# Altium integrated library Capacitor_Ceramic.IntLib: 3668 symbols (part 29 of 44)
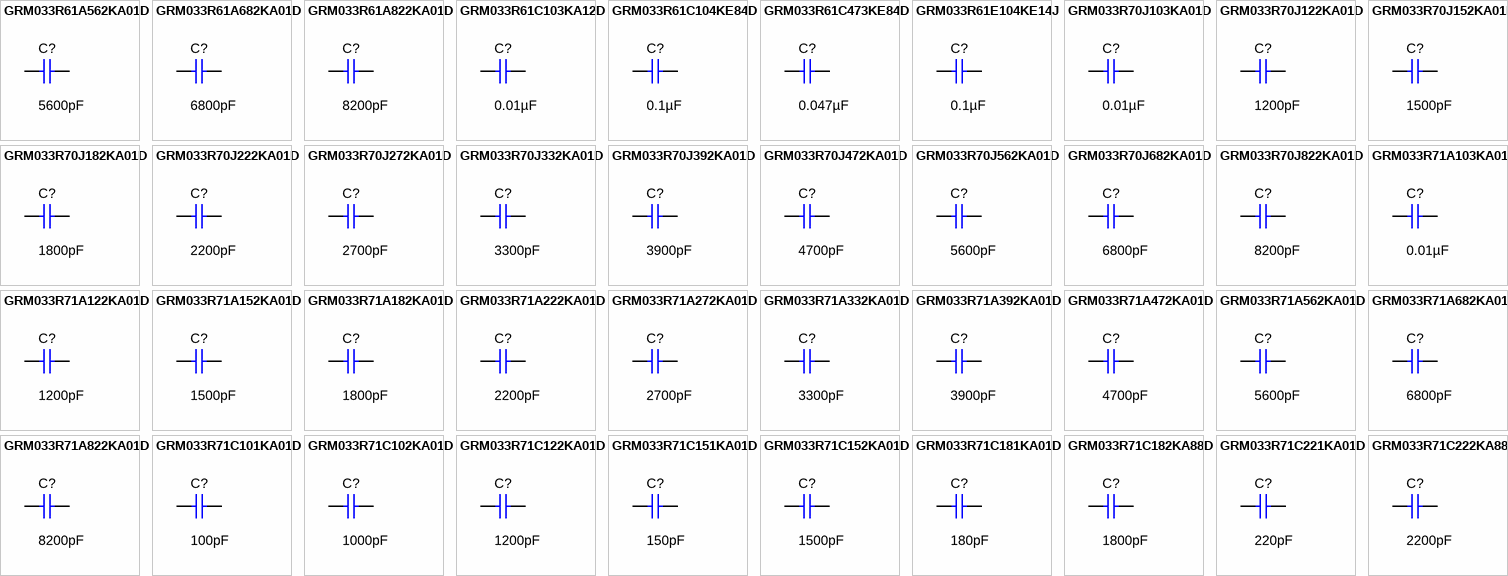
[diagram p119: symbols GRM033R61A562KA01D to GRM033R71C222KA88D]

## GRM033R70J182KA01D
designator C?  ValueDisplayed: 1800pF  (hidden comment: GRM033R70J182KA01D)
CAP, CERM, 1800 pF, 6.3 V,+/- 10%, X7R, 0201; Manufacturer: MuRata; Polarized: N; CompType: Capacitor; Value: 1800pF; U/M: EA; Cap_F: 0.0000000018; Tolerance_%: 10; VDC_V: 6.3; Value2: 6.3V; TaMin_C: -55; TaMax_C: 125; Cap_Case: 0201; SizeArea_mm2: 0.18; SizeAreaWB_mm2: 2.08; SizeX_mm: 0.6; SizeY_mm: 0.3; SizeZ_mm: 0.26; AEC Category: Q200
signal-integrity model Cap
simulation model Cap
footprint 0201
footprint 0201M
footprint 0201L
footprint 0201_Silk
pins: 1, 2

## GRM033R70J222KA01D
designator C?  ValueDisplayed: 2200pF  (hidden comment: GRM033R70J222KA01D)
CAP, CERM, 2200 pF, 6.3 V,+/- 10%, X7R, 0201; Manufacturer: MuRata; Polarized: N; CompType: Capacitor; Value: 2200pF; U/M: EA; Cap_F: 0.0000000022; Tolerance_%: 10; VDC_V: 6.3; Value2: 6.3V; TaMin_C: -55; TaMax_C: 125; Cap_Case: 0201; SizeArea_mm2: 0.18; SizeAreaWB_mm2: 2.08; SizeX_mm: 0.6; SizeY_mm: 0.3; SizeZ_mm: 0.26; AEC Category: Q200
signal-integrity model Cap
simulation model Cap
footprint 0201
footprint 0201M
footprint 0201L
footprint 0201_Silk
pins: 1, 2

## GRM033R70J272KA01D
designator C?  ValueDisplayed: 2700pF  (hidden comment: GRM033R70J272KA01D)
CAP, CERM, 2700 pF, 6.3 V,+/- 10%, X7R, 0201; Manufacturer: MuRata; Polarized: N; CompType: Capacitor; Value: 2700pF; U/M: EA; Cap_F: 0.0000000027; Tolerance_%: 10; VDC_V: 6.3; Value2: 6.3V; TaMin_C: -55; TaMax_C: 125; Cap_Case: 0201; SizeArea_mm2: 0.18; SizeAreaWB_mm2: 2.08; SizeX_mm: 0.6; SizeY_mm: 0.3; SizeZ_mm: 0.26; AEC Category: Q200
signal-integrity model Cap
simulation model Cap
footprint 0201
footprint 0201M
footprint 0201L
footprint 0201_Silk
pins: 1, 2

## GRM033R70J332KA01D
designator C?  ValueDisplayed: 3300pF  (hidden comment: GRM033R70J332KA01D)
CAP, CERM, 3300 pF, 6.3 V,+/- 10%, X7R, 0201; Manufacturer: MuRata; Polarized: N; CompType: Capacitor; Value: 3300pF; U/M: EA; Cap_F: 0.0000000033; Tolerance_%: 10; VDC_V: 6.3; Value2: 6.3V; TaMin_C: -55; TaMax_C: 125; Cap_Case: 0201; SizeArea_mm2: 0.18; SizeAreaWB_mm2: 2.08; SizeX_mm: 0.6; SizeY_mm: 0.3; SizeZ_mm: 0.26; AEC Category: Q200
signal-integrity model Cap
simulation model Cap
footprint 0201
footprint 0201M
footprint 0201L
footprint 0201_Silk
pins: 1, 2

## GRM033R70J392KA01D
designator C?  ValueDisplayed: 3900pF  (hidden comment: GRM033R70J392KA01D)
CAP, CERM, 3900 pF, 6.3 V,+/- 10%, X7R, 0201; Manufacturer: MuRata; Polarized: N; CompType: Capacitor; Value: 3900pF; U/M: EA; Cap_F: 0.0000000039; Tolerance_%: 10; VDC_V: 6.3; Value2: 6.3V; TaMin_C: -55; TaMax_C: 125; Cap_Case: 0201; SizeArea_mm2: 0.18; SizeAreaWB_mm2: 2.08; SizeX_mm: 0.6; SizeY_mm: 0.3; SizeZ_mm: 0.26; AEC Category: Q200
signal-integrity model Cap
simulation model Cap
footprint 0201
footprint 0201M
footprint 0201L
footprint 0201_Silk
pins: 1, 2

## GRM033R70J472KA01D
designator C?  ValueDisplayed: 4700pF  (hidden comment: GRM033R70J472KA01D)
CAP, CERM, 4700 pF, 6.3 V,+/- 10%, X7R, 0201; Manufacturer: MuRata; Polarized: N; CompType: Capacitor; Value: 4700pF; U/M: EA; Cap_F: 0.0000000047; Tolerance_%: 10; VDC_V: 6.3; Value2: 6.3V; TaMin_C: -55; TaMax_C: 125; Cap_Case: 0201; SizeArea_mm2: 0.18; SizeAreaWB_mm2: 2.08; SizeX_mm: 0.6; SizeY_mm: 0.3; SizeZ_mm: 0.26; AEC Category: Q200
signal-integrity model Cap
simulation model Cap
footprint 0201
footprint 0201M
footprint 0201L
footprint 0201_Silk
pins: 1, 2

## GRM033R70J562KA01D
designator C?  ValueDisplayed: 5600pF  (hidden comment: GRM033R70J562KA01D)
CAP, CERM, 5600 pF, 6.3 V,+/- 10%, X7R, 0201; Manufacturer: MuRata; Polarized: N; CompType: Capacitor; Value: 5600pF; U/M: EA; Cap_F: 0.0000000056; Tolerance_%: 10; VDC_V: 6.3; Value2: 6.3V; TaMin_C: -55; TaMax_C: 125; Cap_Case: 0201; SizeArea_mm2: 0.18; SizeAreaWB_mm2: 2.08; SizeX_mm: 0.6; SizeY_mm: 0.3; SizeZ_mm: 0.26; AEC Category: Q200
signal-integrity model Cap
simulation model Cap
footprint 0201
footprint 0201M
footprint 0201L
footprint 0201_Silk
pins: 1, 2

## GRM033R70J682KA01D
designator C?  ValueDisplayed: 6800pF  (hidden comment: GRM033R70J682KA01D)
CAP, CERM, 6800 pF, 6.3 V,+/- 10%, X7R, 0201; Manufacturer: MuRata; Polarized: N; CompType: Capacitor; Value: 6800pF; U/M: EA; Cap_F: 0.0000000068; Tolerance_%: 10; VDC_V: 6.3; Value2: 6.3V; TaMin_C: -55; TaMax_C: 125; Cap_Case: 0201; SizeArea_mm2: 0.18; SizeAreaWB_mm2: 2.08; SizeX_mm: 0.6; SizeY_mm: 0.3; SizeZ_mm: 0.26; AEC Category: Q200
signal-integrity model Cap
simulation model Cap
footprint 0201
footprint 0201M
footprint 0201L
footprint 0201_Silk
pins: 1, 2

## GRM033R70J822KA01D
designator C?  ValueDisplayed: 8200pF  (hidden comment: GRM033R70J822KA01D)
CAP, CERM, 8200 pF, 6.3 V,+/- 10%, X7R, 0201; Manufacturer: MuRata; Polarized: N; CompType: Capacitor; Value: 8200pF; U/M: EA; Cap_F: 0.0000000082; Tolerance_%: 10; VDC_V: 6.3; Value2: 6.3V; TaMin_C: -55; TaMax_C: 125; Cap_Case: 0201; SizeArea_mm2: 0.18; SizeAreaWB_mm2: 2.08; SizeX_mm: 0.6; SizeY_mm: 0.3; SizeZ_mm: 0.26; AEC Category: Q200
signal-integrity model Cap
simulation model Cap
footprint 0201
footprint 0201M
footprint 0201L
footprint 0201_Silk
pins: 1, 2

## GRM033R71A103KA01D
designator C?  ValueDisplayed: 0.01µF  (hidden comment: GRM033R71A103KA01D)
CAP, CERM, 0.01 µF, 10 V,+/- 10%, X7R, 0201; Manufacturer: MuRata; Polarized: N; CompType: Capacitor; Value: 0.01uF; U/M: EA; Cap_F: 0.00000001; Tolerance_%: 10; Value2: 10V; TaMin_C: -55; TaMax_C: 125; Cap_Case: 0201; SizeArea_mm2: 0.18; SizeAreaWB_mm2: 2.08; SizeX_mm: 0.6; SizeY_mm: 0.3; SizeZ_mm: 0.26; AEC Category: Q200; Green_Lifecycle: Active; Green_REACh: Passed
signal-integrity model Cap
simulation model Cap
footprint 0201
footprint 0201M
footprint 0201L
footprint 0201_Silk
pins: 1, 2

## GRM033R71A122KA01D
designator C?  ValueDisplayed: 1200pF  (hidden comment: GRM033R71A122KA01D)
CAP, CERM, 1200 pF, 10 V,+/- 10%, X7R, 0201; Manufacturer: MuRata; Polarized: N; CompType: Capacitor; Value: 1200pF; U/M: EA; Cap_F: 0.0000000012; Tolerance_%: 10; Value2: 10V; TaMin_C: -55; TaMax_C: 125; Cap_Case: 0201; SizeArea_mm2: 0.18; SizeAreaWB_mm2: 2.08; SizeX_mm: 0.6; SizeY_mm: 0.3; SizeZ_mm: 0.26; AEC Category: Q200
signal-integrity model Cap
simulation model Cap
footprint 0201
footprint 0201M
footprint 0201L
footprint 0201_Silk
pins: 1, 2

## GRM033R71A152KA01D
designator C?  ValueDisplayed: 1500pF  (hidden comment: GRM033R71A152KA01D)
CAP, CERM, 1500 pF, 10 V,+/- 10%, X7R, 0201; Manufacturer: MuRata; Polarized: N; CompType: Capacitor; Value: 1500pF; U/M: EA; Cap_F: 0.0000000015; Tolerance_%: 10; Value2: 10V; TaMin_C: -55; TaMax_C: 125; Cap_Case: 0201; SizeArea_mm2: 0.18; SizeAreaWB_mm2: 2.08; SizeX_mm: 0.6; SizeY_mm: 0.3; SizeZ_mm: 0.26; AEC Category: Q200
signal-integrity model Cap
simulation model Cap
footprint 0201
footprint 0201M
footprint 0201L
footprint 0201_Silk
pins: 1, 2

## GRM033R71A182KA01D
designator C?  ValueDisplayed: 1800pF  (hidden comment: GRM033R71A182KA01D)
CAP, CERM, 1800 pF, 10 V,+/- 10%, X7R, 0201; Manufacturer: MuRata; Polarized: N; CompType: Capacitor; Value: 1800pF; U/M: EA; Cap_F: 0.0000000018; Tolerance_%: 10; Value2: 10V; TaMin_C: -55; TaMax_C: 125; Cap_Case: 0201; SizeArea_mm2: 0.18; SizeAreaWB_mm2: 2.08; SizeX_mm: 0.6; SizeY_mm: 0.3; SizeZ_mm: 0.26; AEC Category: Q200
signal-integrity model Cap
simulation model Cap
footprint 0201
footprint 0201M
footprint 0201L
footprint 0201_Silk
pins: 1, 2

## GRM033R71A222KA01D
designator C?  ValueDisplayed: 2200pF  (hidden comment: GRM033R71A222KA01D)
CAP, CERM, 2200 pF, 10 V,+/- 10%, X7R, 0201; Manufacturer: MuRata; Polarized: N; CompType: Capacitor; Value: 2200pF; U/M: EA; Cap_F: 0.0000000022; Tolerance_%: 10; Value2: 10V; TaMin_C: -55; TaMax_C: 125; Cap_Case: 0201; SizeArea_mm2: 0.18; SizeAreaWB_mm2: 2.08; SizeX_mm: 0.6; SizeY_mm: 0.3; SizeZ_mm: 0.26; AEC Category: Q200
signal-integrity model Cap
simulation model Cap
footprint 0201
footprint 0201M
footprint 0201L
footprint 0201_Silk
pins: 1, 2

## GRM033R71A272KA01D
designator C?  ValueDisplayed: 2700pF  (hidden comment: GRM033R71A272KA01D)
CAP, CERM, 2700 pF, 10 V,+/- 10%, X7R, 0201; Manufacturer: MuRata; Polarized: N; CompType: Capacitor; Value: 2700pF; U/M: EA; Cap_F: 0.0000000027; Tolerance_%: 10; Value2: 10V; TaMin_C: -55; TaMax_C: 125; Cap_Case: 0201; SizeArea_mm2: 0.18; SizeAreaWB_mm2: 2.08; SizeX_mm: 0.6; SizeY_mm: 0.3; SizeZ_mm: 0.26; AEC Category: Q200
signal-integrity model Cap
simulation model Cap
footprint 0201
footprint 0201M
footprint 0201L
footprint 0201_Silk
pins: 1, 2

## GRM033R71A332KA01D
designator C?  ValueDisplayed: 3300pF  (hidden comment: GRM033R71A332KA01D)
CAP, CERM, 3300 pF, 10 V,+/- 10%, X7R, 0201; Manufacturer: MuRata; Polarized: N; CompType: Capacitor; Value: 3300pF; U/M: EA; Cap_F: 0.0000000033; Tolerance_%: 10; Value2: 10V; TaMin_C: -55; TaMax_C: 125; Cap_Case: 0201; SizeArea_mm2: 0.18; SizeAreaWB_mm2: 2.08; SizeX_mm: 0.6; SizeY_mm: 0.3; SizeZ_mm: 0.26; AEC Category: Q200
signal-integrity model Cap
simulation model Cap
footprint 0201
footprint 0201M
footprint 0201L
footprint 0201_Silk
pins: 1, 2

## GRM033R71A392KA01D
designator C?  ValueDisplayed: 3900pF  (hidden comment: GRM033R71A392KA01D)
CAP, CERM, 3900 pF, 10 V,+/- 10%, X7R, 0201; Manufacturer: MuRata; Polarized: N; CompType: Capacitor; Value: 3900pF; U/M: EA; Cap_F: 0.0000000039; Tolerance_%: 10; Value2: 10V; TaMin_C: -55; TaMax_C: 125; Cap_Case: 0201; SizeArea_mm2: 0.18; SizeAreaWB_mm2: 2.08; SizeX_mm: 0.6; SizeY_mm: 0.3; SizeZ_mm: 0.26; AEC Category: Q200
signal-integrity model Cap
simulation model Cap
footprint 0201
footprint 0201M
footprint 0201L
footprint 0201_Silk
pins: 1, 2

## GRM033R71A472KA01D
designator C?  ValueDisplayed: 4700pF  (hidden comment: GRM033R71A472KA01D)
CAP, CERM, 4700 pF, 10 V,+/- 10%, X7R, 0201; Manufacturer: MuRata; Polarized: N; CompType: Capacitor; Value: 4700pF; U/M: EA; Cap_F: 0.0000000047; Tolerance_%: 10; Value2: 10V; TaMin_C: -55; TaMax_C: 125; Cap_Case: 0201; SizeArea_mm2: 0.18; SizeAreaWB_mm2: 2.08; SizeX_mm: 0.6; SizeY_mm: 0.3; SizeZ_mm: 0.26; AEC Category: Q200
signal-integrity model Cap
simulation model Cap
footprint 0201
footprint 0201M
footprint 0201L
footprint 0201_Silk
pins: 1, 2

## GRM033R71A562KA01D
designator C?  ValueDisplayed: 5600pF  (hidden comment: GRM033R71A562KA01D)
CAP, CERM, 5600 pF, 10 V,+/- 10%, X7R, 0201; Manufacturer: MuRata; Polarized: N; CompType: Capacitor; Value: 5600pF; U/M: EA; Cap_F: 0.0000000056; Tolerance_%: 10; Value2: 10V; TaMin_C: -55; TaMax_C: 125; Cap_Case: 0201; SizeArea_mm2: 0.18; SizeAreaWB_mm2: 2.08; SizeX_mm: 0.6; SizeY_mm: 0.3; SizeZ_mm: 0.26; AEC Category: Q200
signal-integrity model Cap
simulation model Cap
footprint 0201
footprint 0201M
footprint 0201L
footprint 0201_Silk
pins: 1, 2

## GRM033R71A682KA01D
designator C?  ValueDisplayed: 6800pF  (hidden comment: GRM033R71A682KA01D)
CAP, CERM, 6800 pF, 10 V,+/- 10%, X7R, 0201; Manufacturer: MuRata; Polarized: N; CompType: Capacitor; Value: 6800pF; U/M: EA; Cap_F: 0.0000000068; Tolerance_%: 10; Value2: 10V; TaMin_C: -55; TaMax_C: 125; Cap_Case: 0201; SizeArea_mm2: 0.18; SizeAreaWB_mm2: 2.08; SizeX_mm: 0.6; SizeY_mm: 0.3; SizeZ_mm: 0.26; AEC Category: Q200; Green_Lifecycle: Active; Green_REACh: Passed
signal-integrity model Cap
simulation model Cap
footprint 0201
footprint 0201M
footprint 0201L
footprint 0201_Silk
pins: 1, 2

## GRM033R71A822KA01D
designator C?  ValueDisplayed: 8200pF  (hidden comment: GRM033R71A822KA01D)
CAP, CERM, 8200 pF, 10 V,+/- 10%, X7R, 0201; Manufacturer: MuRata; Polarized: N; CompType: Capacitor; Value: 8200pF; U/M: EA; Cap_F: 0.0000000082; Tolerance_%: 10; Value2: 10V; TaMin_C: -55; TaMax_C: 125; Cap_Case: 0201; SizeArea_mm2: 0.18; SizeAreaWB_mm2: 2.08; SizeX_mm: 0.6; SizeY_mm: 0.3; SizeZ_mm: 0.26; AEC Category: Q200
signal-integrity model Cap
simulation model Cap
footprint 0201
footprint 0201M
footprint 0201L
footprint 0201_Silk
pins: 1, 2

## GRM033R71C101KA01D
designator C?  ValueDisplayed: 100pF  (hidden comment: GRM033R71C101KA01D)
CAP, CERM, 100 pF, 16 V,+/- 10%, X7R, 0201; Manufacturer: MuRata; Polarized: N; CompType: Capacitor; Value: 100pF; U/M: EA; Cap_F: 0.0000000001; Tolerance_%: 10; VDC_V: 16; Value2: 16V; TaMin_C: -55; TaMax_C: 125; Cap_Case: 0201; SizeArea_mm2: 0.18; SizeAreaWB_mm2: 2.08; SizeX_mm: 0.6; SizeY_mm: 0.3; SizeZ_mm: 0.26; AEC Category: Q200; Green_Lifecycle: Active; Green_REACh: Passed
signal-integrity model Cap
simulation model Cap
footprint 0201
footprint 0201M
footprint 0201L
footprint 0201_Silk
pins: 1, 2

## GRM033R71C102KA01D
designator C?  ValueDisplayed: 1000pF  (hidden comment: GRM033R71C102KA01D)
CAP, CERM, 1000 pF, 16 V,+/- 10%, X7R, 0201; Manufacturer: MuRata; Polarized: N; CompType: Capacitor; Value: 1000pF; U/M: EA; Cap_F: 0.000000001; Tolerance_%: 10; VDC_V: 16; Value2: 16V; TaMin_C: -55; TaMax_C: 125; Cap_Case: 0201; SizeArea_mm2: 0.18; SizeAreaWB_mm2: 2.08; SizeX_mm: 0.6; SizeY_mm: 0.3; SizeZ_mm: 0.26; AEC Category: Q200
signal-integrity model Cap
simulation model Cap
footprint 0201
footprint 0201M
footprint 0201L
footprint 0201_Silk
pins: 1, 2

## GRM033R71C122KA01D
designator C?  ValueDisplayed: 1200pF  (hidden comment: GRM033R71C122KA01D)
CAP, CERM, 1200 pF, 16 V,+/- 10%, X7R, 0201; Manufacturer: MuRata; Polarized: N; CompType: Capacitor; Value: 1200pF; U/M: EA; Cap_F: 0.0000000012; Tolerance_%: 10; VDC_V: 16; Value2: 16V; TaMin_C: -55; TaMax_C: 125; Cap_Case: 0201; SizeArea_mm2: 0.18; SizeAreaWB_mm2: 2.08; SizeX_mm: 0.6; SizeY_mm: 0.3; SizeZ_mm: 0.26; AEC Category: Q200
signal-integrity model Cap
simulation model Cap
footprint 0201
footprint 0201M
footprint 0201L
footprint 0201_Silk
pins: 1, 2

## GRM033R71C151KA01D
designator C?  ValueDisplayed: 150pF  (hidden comment: GRM033R71C151KA01D)
CAP, CERM, 150 pF, 16 V,+/- 10%, X7R, 0201; Manufacturer: MuRata; Polarized: N; CompType: Capacitor; Value: 150pF; U/M: EA; Cap_F: 0.00000000015; Tolerance_%: 10; VDC_V: 16; Value2: 16V; TaMin_C: -55; TaMax_C: 125; Cap_Case: 0201; SizeArea_mm2: 0.18; SizeAreaWB_mm2: 2.08; SizeX_mm: 0.6; SizeY_mm: 0.3; SizeZ_mm: 0.26; AEC Category: Q200
signal-integrity model Cap
simulation model Cap
footprint 0201
footprint 0201M
footprint 0201L
footprint 0201_Silk
pins: 1, 2

## GRM033R71C152KA01D
designator C?  ValueDisplayed: 1500pF  (hidden comment: GRM033R71C152KA01D)
CAP, CERM, 1500 pF, 16 V,+/- 10%, X7R, 0201; Manufacturer: MuRata; Polarized: N; CompType: Capacitor; Value: 1500pF; U/M: EA; Cap_F: 0.0000000015; Tolerance_%: 10; VDC_V: 16; Value2: 16V; TaMin_C: -55; TaMax_C: 125; Cap_Case: 0201; SizeArea_mm2: 0.18; SizeAreaWB_mm2: 2.08; SizeX_mm: 0.6; SizeY_mm: 0.3; SizeZ_mm: 0.26; AEC Category: Q200
signal-integrity model Cap
simulation model Cap
footprint 0201
footprint 0201M
footprint 0201L
footprint 0201_Silk
pins: 1, 2

## GRM033R71C181KA01D
designator C?  ValueDisplayed: 180pF  (hidden comment: GRM033R71C181KA01D)
CAP, CERM, 180 pF, 16 V,+/- 10%, X7R, 0201; Manufacturer: MuRata; Polarized: N; CompType: Capacitor; Value: 180pF; U/M: EA; Cap_F: 0.00000000018; Tolerance_%: 10; VDC_V: 16; Value2: 16V; TaMin_C: -55; TaMax_C: 125; Cap_Case: 0201; SizeArea_mm2: 0.18; SizeAreaWB_mm2: 2.08; SizeX_mm: 0.6; SizeY_mm: 0.3; SizeZ_mm: 0.26; AEC Category: Q200
signal-integrity model Cap
simulation model Cap
footprint 0201
footprint 0201M
footprint 0201L
footprint 0201_Silk
pins: 1, 2

## GRM033R71C182KA88D
designator C?  ValueDisplayed: 1800pF  (hidden comment: GRM033R71C182KA88D)
CAP, CERM, 1800 pF, 16 V,+/- 10%, X7R, 0201; Manufacturer: MuRata; Polarized: N; CompType: Capacitor; Value: 1800pF; U/M: EA; Cap_F: 0.0000000018; Tolerance_%: 10; VDC_V: 16; Value2: 16V; TaMin_C: -55; TaMax_C: 125; Cap_Case: 0201; SizeArea_mm2: 0.18; SizeAreaWB_mm2: 2.08; SizeX_mm: 0.6; SizeY_mm: 0.3; SizeZ_mm: 0.26; AEC Category: Q200
signal-integrity model Cap
simulation model Cap
footprint 0201
footprint 0201M
footprint 0201L
footprint 0201_Silk
pins: 1, 2

## GRM033R71C221KA01D
designator C?  ValueDisplayed: 220pF  (hidden comment: GRM033R71C221KA01D)
CAP, CERM, 220 pF, 16 V,+/- 10%, X7R, 0201; Manufacturer: MuRata; Polarized: N; CompType: Capacitor; Value: 220pF; U/M: EA; Cap_F: 0.00000000022; Tolerance_%: 10; VDC_V: 16; Value2: 16V; TaMin_C: -55; TaMax_C: 125; Cap_Case: 0201; SizeArea_mm2: 0.18; SizeAreaWB_mm2: 2.08; SizeX_mm: 0.6; SizeY_mm: 0.3; SizeZ_mm: 0.26; AEC Category: Q200
signal-integrity model Cap
simulation model Cap
footprint 0201
footprint 0201M
footprint 0201L
footprint 0201_Silk
pins: 1, 2

## GRM033R71C222KA88D
designator C?  ValueDisplayed: 2200pF  (hidden comment: GRM033R71C222KA88D)
CAP, CERM, 2200 pF, 16 V,+/- 10%, X7R, 0201; Manufacturer: MuRata; Polarized: N; CompType: Capacitor; Value: 2200pF; U/M: EA; Cap_F: 0.0000000022; Tolerance_%: 10; VDC_V: 16; Value2: 16V; TaMin_C: -55; TaMax_C: 125; Cap_Case: 0201; SizeArea_mm2: 0.18; SizeAreaWB_mm2: 2.08; SizeX_mm: 0.6; SizeY_mm: 0.3; SizeZ_mm: 0.26; AEC Category: Q200
signal-integrity model Cap
simulation model Cap
footprint 0201
footprint 0201M
footprint 0201L
footprint 0201_Silk
pins: 1, 2

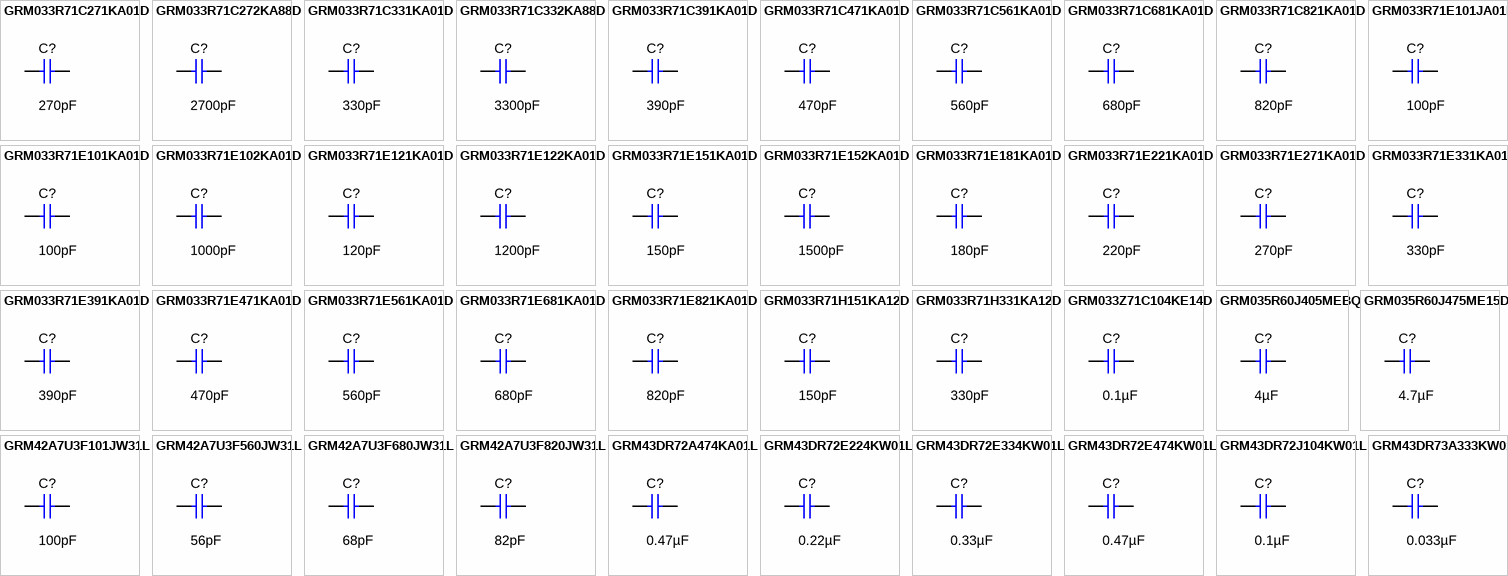
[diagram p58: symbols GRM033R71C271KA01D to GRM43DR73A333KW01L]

## GRM033R71C271KA01D
designator C?  ValueDisplayed: 270pF  (hidden comment: GRM033R71C271KA01D)
CAP, CERM, 270 pF, 16 V,+/- 10%, X7R, 0201; Manufacturer: MuRata; Polarized: N; CompType: Capacitor; Value: 270pF; U/M: EA; Cap_F: 0.00000000027; Tolerance_%: 10; VDC_V: 16; Value2: 16V; TaMin_C: -55; TaMax_C: 125; Cap_Case: 0201; SizeArea_mm2: 0.18; SizeAreaWB_mm2: 2.08; SizeX_mm: 0.6; SizeY_mm: 0.3; SizeZ_mm: 0.26; AEC Category: Q200
signal-integrity model Cap
simulation model Cap
footprint 0201
footprint 0201M
footprint 0201L
footprint 0201_Silk
pins: 1, 2

## GRM033R71C272KA88D
designator C?  ValueDisplayed: 2700pF  (hidden comment: GRM033R71C272KA88D)
CAP, CERM, 2700 pF, 16 V,+/- 10%, X7R, 0201; Manufacturer: MuRata; Polarized: N; CompType: Capacitor; Value: 2700pF; U/M: EA; Cap_F: 0.0000000027; Tolerance_%: 10; VDC_V: 16; Value2: 16V; TaMin_C: -55; TaMax_C: 125; Cap_Case: 0201; SizeArea_mm2: 0.18; SizeAreaWB_mm2: 2.08; SizeX_mm: 0.6; SizeY_mm: 0.3; SizeZ_mm: 0.26; AEC Category: Q200
signal-integrity model Cap
simulation model Cap
footprint 0201
footprint 0201M
footprint 0201L
footprint 0201_Silk
pins: 1, 2

## GRM033R71C331KA01D
designator C?  ValueDisplayed: 330pF  (hidden comment: GRM033R71C331KA01D)
CAP, CERM, 330 pF, 16 V,+/- 10%, X7R, 0201; Manufacturer: MuRata; Polarized: N; CompType: Capacitor; Value: 330pF; U/M: EA; Cap_F: 0.00000000033; Tolerance_%: 10; VDC_V: 16; Value2: 16V; TaMin_C: -55; TaMax_C: 125; Cap_Case: 0201; SizeArea_mm2: 0.18; SizeAreaWB_mm2: 2.08; SizeX_mm: 0.6; SizeY_mm: 0.3; SizeZ_mm: 0.26; AEC Category: Q200; Green_Lifecycle: Active; Green_REACh: Passed
signal-integrity model Cap
simulation model Cap
footprint 0201
footprint 0201M
footprint 0201L
footprint 0201_Silk
pins: 1, 2

## GRM033R71C332KA88D
designator C?  ValueDisplayed: 3300pF  (hidden comment: GRM033R71C332KA88D)
CAP, CERM, 3300 pF, 16 V,+/- 10%, X7R, 0201; Manufacturer: MuRata; Polarized: N; CompType: Capacitor; Value: 3300pF; U/M: EA; Cap_F: 0.0000000033; Tolerance_%: 10; VDC_V: 16; Value2: 16V; TaMin_C: -55; TaMax_C: 125; Cap_Case: 0201; SizeArea_mm2: 0.18; SizeAreaWB_mm2: 2.08; SizeX_mm: 0.6; SizeY_mm: 0.3; SizeZ_mm: 0.26; AEC Category: Q200
signal-integrity model Cap
simulation model Cap
footprint 0201
footprint 0201M
footprint 0201L
footprint 0201_Silk
pins: 1, 2

## GRM033R71C391KA01D
designator C?  ValueDisplayed: 390pF  (hidden comment: GRM033R71C391KA01D)
CAP, CERM, 390 pF, 16 V,+/- 10%, X7R, 0201; Manufacturer: MuRata; Polarized: N; CompType: Capacitor; Value: 390pF; U/M: EA; Cap_F: 0.00000000039; Tolerance_%: 10; VDC_V: 16; Value2: 16V; TaMin_C: -55; TaMax_C: 125; Cap_Case: 0201; SizeArea_mm2: 0.18; SizeAreaWB_mm2: 2.08; SizeX_mm: 0.6; SizeY_mm: 0.3; SizeZ_mm: 0.26; AEC Category: Q200
signal-integrity model Cap
simulation model Cap
footprint 0201
footprint 0201M
footprint 0201L
footprint 0201_Silk
pins: 1, 2

## GRM033R71C471KA01D
designator C?  ValueDisplayed: 470pF  (hidden comment: GRM033R71C471KA01D)
CAP, CERM, 470 pF, 16 V,+/- 10%, X7R, 0201; Manufacturer: MuRata; Polarized: N; CompType: Capacitor; Value: 470pF; U/M: EA; Cap_F: 0.00000000047; Tolerance_%: 10; VDC_V: 16; Value2: 16V; TaMin_C: -55; TaMax_C: 125; Cap_Case: 0201; SizeArea_mm2: 0.18; SizeAreaWB_mm2: 2.08; SizeX_mm: 0.6; SizeY_mm: 0.3; SizeZ_mm: 0.26; AEC Category: Q200
signal-integrity model Cap
simulation model Cap
footprint 0201
footprint 0201M
footprint 0201L
footprint 0201_Silk
pins: 1, 2

## GRM033R71C561KA01D
designator C?  ValueDisplayed: 560pF  (hidden comment: GRM033R71C561KA01D)
CAP, CERM, 560 pF, 16 V,+/- 10%, X7R, 0201; Manufacturer: MuRata; Polarized: N; CompType: Capacitor; Value: 560pF; U/M: EA; Cap_F: 0.00000000056; Tolerance_%: 10; VDC_V: 16; Value2: 16V; TaMin_C: -55; TaMax_C: 125; Cap_Case: 0201; SizeArea_mm2: 0.18; SizeAreaWB_mm2: 2.08; SizeX_mm: 0.6; SizeY_mm: 0.3; SizeZ_mm: 0.26; AEC Category: Q200
signal-integrity model Cap
simulation model Cap
footprint 0201
footprint 0201M
footprint 0201L
footprint 0201_Silk
pins: 1, 2

## GRM033R71C681KA01D
designator C?  ValueDisplayed: 680pF  (hidden comment: GRM033R71C681KA01D)
CAP, CERM, 680 pF, 16 V,+/- 10%, X7R, 0201; Manufacturer: MuRata; Polarized: N; CompType: Capacitor; Value: 680pF; U/M: EA; Cap_F: 0.00000000068; Tolerance_%: 10; VDC_V: 16; Value2: 16V; TaMin_C: -55; TaMax_C: 125; Cap_Case: 0201; SizeArea_mm2: 0.18; SizeAreaWB_mm2: 2.08; SizeX_mm: 0.6; SizeY_mm: 0.3; SizeZ_mm: 0.26; AEC Category: Q200
signal-integrity model Cap
simulation model Cap
footprint 0201
footprint 0201M
footprint 0201L
footprint 0201_Silk
pins: 1, 2

## GRM033R71C821KA01D
designator C?  ValueDisplayed: 820pF  (hidden comment: GRM033R71C821KA01D)
CAP, CERM, 820 pF, 16 V,+/- 10%, X7R, 0201; Manufacturer: MuRata; Polarized: N; CompType: Capacitor; Value: 820pF; U/M: EA; Cap_F: 0.00000000082; Tolerance_%: 10; VDC_V: 16; Value2: 16V; TaMin_C: -55; TaMax_C: 125; Cap_Case: 0201; SizeArea_mm2: 0.18; SizeAreaWB_mm2: 2.08; SizeX_mm: 0.6; SizeY_mm: 0.3; SizeZ_mm: 0.26; AEC Category: Q200
signal-integrity model Cap
simulation model Cap
footprint 0201
footprint 0201M
footprint 0201L
footprint 0201_Silk
pins: 1, 2

## GRM033R71E101JA01D
designator C?  ValueDisplayed: 100pF  (hidden comment: GRM033R71E101JA01D)
CAP, CERM, 100 pF, 25 V,+/- 5%, C0G/NP0, 0201; Manufacturer: MuRata; Polarized: N; CompType: Capacitor; Value: 100pF; U/M: EA; Cap_F: 0.0000000001; Tolerance_%: 5; VDC_V: 25; Value2: 25V; TaMin_C: -55; TaMax_C: 125; Cap_Case: 0201; SizeArea_mm2: 0.18; SizeAreaWB_mm2: 2.08; SizeX_mm: 0.6; SizeY_mm: 0.3; SizeZ_mm: 0.33; AEC Category: Q200
signal-integrity model Cap
simulation model Cap
footprint 0201_033
footprint 0201_033M
footprint 0201_033L
pins: 1, 2

## GRM033R71E101KA01D
designator C?  ValueDisplayed: 100pF  (hidden comment: GRM033R71E101KA01D)
CAP, CERM, 100 pF, 25 V,+/- 10%, X7R, 0201; Manufacturer: MuRata; Polarized: N; CompType: Capacitor; Value: 100pF; U/M: EA; Cap_F: 0.0000000001; Tolerance_%: 10; VDC_V: 25; Value2: 25V; TaMin_C: -55; TaMax_C: 125; Cap_Case: 0201; SizeArea_mm2: 0.18; SizeAreaWB_mm2: 2.08; SizeX_mm: 0.6; SizeY_mm: 0.3; SizeZ_mm: 0.26; AEC Category: Q200; Green_Lifecycle: Active; Green_REACh: Passed
signal-integrity model Cap
simulation model Cap
footprint 0201
footprint 0201M
footprint 0201L
footprint 0201_Silk
pins: 1, 2

## GRM033R71E102KA01D
designator C?  ValueDisplayed: 1000pF  (hidden comment: GRM033R71E102KA01D)
CAP, CERM, 1000 pF, 25 V,+/- 10%, X7R, 0201; Manufacturer: MuRata; Polarized: N; CompType: Capacitor; Value: 1000pF; U/M: EA; Cap_F: 0.000000001; Tolerance_%: 10; VDC_V: 25; Value2: 25V; TaMin_C: -55; TaMax_C: 125; Cap_Case: 0201; SizeArea_mm2: 0.18; SizeAreaWB_mm2: 2.08; SizeX_mm: 0.6; SizeY_mm: 0.3; SizeZ_mm: 0.33; AEC Category: Q200; Green_Lifecycle: Active; Green_REACh: Passed
signal-integrity model Cap
simulation model Cap
footprint 0201_033
footprint 0201_033M
footprint 0201_033L
pins: 1, 2

## GRM033R71E121KA01D
designator C?  ValueDisplayed: 120pF  (hidden comment: GRM033R71E121KA01D)
CAP, CERM, 120 pF, 25 V,+/- 10%, X7R, 0201; Manufacturer: MuRata; Polarized: N; CompType: Capacitor; Value: 120pF; U/M: EA; Cap_F: 0.00000000012; Tolerance_%: 10; VDC_V: 25; Value2: 25V; TaMin_C: -55; TaMax_C: 125; Cap_Case: 0201; SizeArea_mm2: 0.18; SizeAreaWB_mm2: 2.08; SizeX_mm: 0.6; SizeY_mm: 0.3; SizeZ_mm: 0.26; AEC Category: Q200
signal-integrity model Cap
simulation model Cap
footprint 0201
footprint 0201M
footprint 0201L
footprint 0201_Silk
pins: 1, 2

## GRM033R71E122KA01D
designator C?  ValueDisplayed: 1200pF  (hidden comment: GRM033R71E122KA01D)
CAP, CERM, 1200 pF, 25 V,+/- 10%, X7R, 0201; Manufacturer: MuRata; Polarized: N; CompType: Capacitor; Value: 1200pF; U/M: EA; Cap_F: 0.0000000012; Tolerance_%: 10; VDC_V: 25; Value2: 25V; TaMin_C: -55; TaMax_C: 125; Cap_Case: 0201; SizeArea_mm2: 0.18; SizeAreaWB_mm2: 2.08; SizeX_mm: 0.6; SizeY_mm: 0.3; SizeZ_mm: 0.26; AEC Category: Q200
signal-integrity model Cap
simulation model Cap
footprint 0201
footprint 0201M
footprint 0201L
footprint 0201_Silk
pins: 1, 2

## GRM033R71E151KA01D
designator C?  ValueDisplayed: 150pF  (hidden comment: GRM033R71E151KA01D)
CAP, CERM, 150 pF, 25 V,+/- 10%, X7R, 0201; Manufacturer: MuRata; Polarized: N; CompType: Capacitor; Value: 150pF; U/M: EA; Cap_F: 0.00000000015; Tolerance_%: 10; VDC_V: 25; Value2: 25V; TaMin_C: -55; TaMax_C: 125; Cap_Case: 0201; SizeArea_mm2: 0.18; SizeAreaWB_mm2: 2.08; SizeX_mm: 0.6; SizeY_mm: 0.3; SizeZ_mm: 0.26; AEC Category: Q200
signal-integrity model Cap
simulation model Cap
footprint 0201
footprint 0201M
footprint 0201L
footprint 0201_Silk
pins: 1, 2

## GRM033R71E152KA01D
designator C?  ValueDisplayed: 1500pF  (hidden comment: GRM033R71E152KA01D)
CAP, CERM, 1500 pF, 25 V,+/- 10%, X7R, 0201; Manufacturer: MuRata; Polarized: N; CompType: Capacitor; Value: 1500pF; U/M: EA; Cap_F: 0.0000000015; Tolerance_%: 10; VDC_V: 25; Value2: 25V; TaMin_C: -55; TaMax_C: 125; Cap_Case: 0201; SizeArea_mm2: 0.18; SizeAreaWB_mm2: 2.08; SizeX_mm: 0.6; SizeY_mm: 0.3; SizeZ_mm: 0.26; AEC Category: Q200
signal-integrity model Cap
simulation model Cap
footprint 0201
footprint 0201M
footprint 0201L
footprint 0201_Silk
pins: 1, 2

## GRM033R71E181KA01D
designator C?  ValueDisplayed: 180pF  (hidden comment: GRM033R71E181KA01D)
CAP, CERM, 180 pF, 25 V,+/- 10%, X7R, 0201; Manufacturer: MuRata; Polarized: N; CompType: Capacitor; Value: 180pF; U/M: EA; Cap_F: 0.00000000018; Tolerance_%: 10; VDC_V: 25; Value2: 25V; TaMin_C: -55; TaMax_C: 125; Cap_Case: 0201; SizeArea_mm2: 0.18; SizeAreaWB_mm2: 2.08; SizeX_mm: 0.6; SizeY_mm: 0.3; SizeZ_mm: 0.26; AEC Category: Q200
signal-integrity model Cap
simulation model Cap
footprint 0201
footprint 0201M
footprint 0201L
footprint 0201_Silk
pins: 1, 2

## GRM033R71E221KA01D
designator C?  ValueDisplayed: 220pF  (hidden comment: GRM033R71E221KA01D)
CAP, CERM, 220 pF, 25 V,+/- 10%, X7R, 0201; Manufacturer: MuRata; Polarized: N; CompType: Capacitor; Value: 220pF; U/M: EA; Cap_F: 0.00000000022; Tolerance_%: 10; VDC_V: 25; Value2: 25V; TaMin_C: -55; TaMax_C: 125; Cap_Case: 0201; SizeArea_mm2: 0.18; SizeAreaWB_mm2: 2.08; SizeX_mm: 0.6; SizeY_mm: 0.3; SizeZ_mm: 0.26; AEC Category: Q200; Green_Lifecycle: Active; Green_REACh: Passed
signal-integrity model Cap
simulation model Cap
footprint 0201
footprint 0201M
footprint 0201L
footprint 0201_Silk
pins: 1, 2

## GRM033R71E271KA01D
designator C?  ValueDisplayed: 270pF  (hidden comment: GRM033R71E271KA01D)
CAP, CERM, 270 pF, 25 V,+/- 10%, X7R, 0201; Manufacturer: MuRata; Polarized: N; CompType: Capacitor; Value: 270pF; U/M: EA; Cap_F: 0.00000000027; Tolerance_%: 10; VDC_V: 25; Value2: 25V; TaMin_C: -55; TaMax_C: 125; Cap_Case: 0201; SizeArea_mm2: 0.18; SizeAreaWB_mm2: 2.08; SizeX_mm: 0.6; SizeY_mm: 0.3; SizeZ_mm: 0.26; AEC Category: Q200
signal-integrity model Cap
simulation model Cap
footprint 0201
footprint 0201M
footprint 0201L
footprint 0201_Silk
pins: 1, 2

## GRM033R71E331KA01D
designator C?  ValueDisplayed: 330pF  (hidden comment: GRM033R71E331KA01D)
CAP, CERM, 330 pF, 25 V,+/- 10%, X7R, 0201; Manufacturer: MuRata; Polarized: N; CompType: Capacitor; Value: 330pF; U/M: EA; Cap_F: 0.00000000033; Tolerance_%: 10; VDC_V: 25; Value2: 25V; TaMin_C: -55; TaMax_C: 125; Cap_Case: 0201; SizeArea_mm2: 0.18; SizeAreaWB_mm2: 2.08; SizeX_mm: 0.6; SizeY_mm: 0.3; SizeZ_mm: 0.26; AEC Category: Q200; Green_Lifecycle: Active; Green_REACh: Passed
signal-integrity model Cap
simulation model Cap
footprint 0201
footprint 0201M
footprint 0201L
footprint 0201_Silk
pins: 1, 2

## GRM033R71E391KA01D
designator C?  ValueDisplayed: 390pF  (hidden comment: GRM033R71E391KA01D)
CAP, CERM, 390 pF, 25 V,+/- 10%, X7R, 0201; Manufacturer: MuRata; Polarized: N; CompType: Capacitor; Value: 390pF; U/M: EA; Cap_F: 0.00000000039; Tolerance_%: 10; VDC_V: 25; Value2: 25V; TaMin_C: -55; TaMax_C: 125; Cap_Case: 0201; SizeArea_mm2: 0.18; SizeAreaWB_mm2: 2.08; SizeX_mm: 0.6; SizeY_mm: 0.3; SizeZ_mm: 0.26; AEC Category: Q200
signal-integrity model Cap
simulation model Cap
footprint 0201
footprint 0201M
footprint 0201L
footprint 0201_Silk
pins: 1, 2

## GRM033R71E471KA01D
designator C?  ValueDisplayed: 470pF  (hidden comment: GRM033R71E471KA01D)
CAP, CERM, 470 pF, 25 V,+/- 10%, X7R, 0201; Manufacturer: MuRata; Polarized: N; CompType: Capacitor; Value: 470pF; U/M: EA; Cap_F: 0.00000000047; Tolerance_%: 10; VDC_V: 25; Value2: 25V; TaMin_C: -55; TaMax_C: 125; Cap_Case: 0201; SizeArea_mm2: 0.18; SizeAreaWB_mm2: 2.08; SizeX_mm: 0.6; SizeY_mm: 0.3; SizeZ_mm: 0.26; AEC Category: Q200
signal-integrity model Cap
simulation model Cap
footprint 0201
footprint 0201M
footprint 0201L
footprint 0201_Silk
pins: 1, 2

## GRM033R71E561KA01D
designator C?  ValueDisplayed: 560pF  (hidden comment: GRM033R71E561KA01D)
CAP, CERM, 560 pF, 25 V,+/- 10%, X7R, 0201; Manufacturer: MuRata; Polarized: N; CompType: Capacitor; Value: 560pF; U/M: EA; Cap_F: 0.00000000056; Tolerance_%: 10; VDC_V: 25; Value2: 25V; TaMin_C: -55; TaMax_C: 125; Cap_Case: 0201; SizeArea_mm2: 0.18; SizeAreaWB_mm2: 2.08; SizeX_mm: 0.6; SizeY_mm: 0.3; SizeZ_mm: 0.26; AEC Category: Q200; Green_Lifecycle: Active; Green_REACh: Passed
signal-integrity model Cap
simulation model Cap
footprint 0201
footprint 0201M
footprint 0201L
footprint 0201_Silk
pins: 1, 2

## GRM033R71E681KA01D
designator C?  ValueDisplayed: 680pF  (hidden comment: GRM033R71E681KA01D)
CAP, CERM, 680 pF, 25 V,+/- 10%, X7R, 0201; Manufacturer: MuRata; Polarized: N; CompType: Capacitor; Value: 680pF; U/M: EA; Cap_F: 0.00000000068; Tolerance_%: 10; VDC_V: 25; Value2: 25V; TaMin_C: -55; TaMax_C: 125; Cap_Case: 0201; SizeArea_mm2: 0.18; SizeAreaWB_mm2: 2.08; SizeX_mm: 0.6; SizeY_mm: 0.3; SizeZ_mm: 0.26; AEC Category: Q200
signal-integrity model Cap
simulation model Cap
footprint 0201
footprint 0201M
footprint 0201L
footprint 0201_Silk
pins: 1, 2

## GRM033R71E821KA01D
designator C?  ValueDisplayed: 820pF  (hidden comment: GRM033R71E821KA01D)
CAP, CERM, 820 pF, 25 V,+/- 10%, X7R, 0201; Manufacturer: MuRata; Polarized: N; CompType: Capacitor; Value: 820pF; U/M: EA; Cap_F: 0.00000000082; Tolerance_%: 10; VDC_V: 25; Value2: 25V; TaMin_C: -55; TaMax_C: 125; Cap_Case: 0201; SizeArea_mm2: 0.18; SizeAreaWB_mm2: 2.08; SizeX_mm: 0.6; SizeY_mm: 0.3; SizeZ_mm: 0.26; AEC Category: Q200
signal-integrity model Cap
simulation model Cap
footprint 0201
footprint 0201M
footprint 0201L
footprint 0201_Silk
pins: 1, 2

## GRM033R71H151KA12D
designator C?  ValueDisplayed: 150pF  (hidden comment: GRM033R71H151KA12D)
CAP, CERM, 150 pF, 50 V,+/- 10%, X7R, 0201; Manufacturer: MuRata; Polarized: N; CompType: Capacitor; Value: 150pF; U/M: EA; Cap_F: 0.00000000015; Tolerance_%: 10; VDC_V: 50; Value2: 50V; TaMin_C: -55; TaMax_C: 125; Cap_Case: 0201; SizeArea_mm2: 0.18; SizeAreaWB_mm2: 2.08; SizeX_mm: 0.6; SizeY_mm: 0.3; SizeZ_mm: 0.33; AEC Category: Q200
signal-integrity model Cap
simulation model Cap
footprint 0201_033
footprint 0201_033M
footprint 0201_033L
pins: 1, 2

## GRM033R71H331KA12D
designator C?  ValueDisplayed: 330pF  (hidden comment: GRM033R71H331KA12D)
CAP, CERM, 330 pF, 50 V,+/- 10%, X7R, 0201; Manufacturer: MuRata; Polarized: N; CompType: Capacitor; Value: 330pF; U/M: EA; Cap_F: 0.00000000033; Tolerance_%: 10; VDC_V: 50; Value2: 50V; TaMin_C: -55; TaMax_C: 125; Cap_Case: 0201; SizeArea_mm2: 0.18; SizeAreaWB_mm2: 2.08; SizeX_mm: 0.6; SizeY_mm: 0.3; SizeZ_mm: 0.33; AEC Category: Q200
signal-integrity model Cap
simulation model Cap
footprint 0201_033
footprint 0201_033M
footprint 0201_033L
pins: 1, 2

## GRM033Z71C104KE14D
designator C?  ValueDisplayed: 0.1µF  (hidden comment: GRM033Z71C104KE14D)
CAP, CERM, 0.1 µF, 16 V,+/- 10%, X7R, 0201; Manufacturer: MuRata; Polarized: N; CompType: Capacitor; Value: 0.1uF; U/M: EA; Cap_F: 0.0000001; Tolerance_%: 10; VDC_V: 16; Value2: 16V; TaMin_C: -55; TaMax_C: 125; Cap_Case: 0201; SizeArea_mm2: 0.18; SizeAreaWB_mm2: 2.08; SizeX_mm: 0.6; SizeY_mm: 0.3; SizeZ_mm: 0.26; AEC Category: Q200
signal-integrity model Cap
simulation model Cap
footprint 0201
footprint 0201M
footprint 0201L
footprint 0201_Silk
pins: 1, 2

## GRM035R60J405MEBQ
designator C?  ValueDisplayed: 4µF  (hidden comment: GRM035R60J405MEBQ)
CAP, CERM, 4 µF, 6.3 V,+/- 20%, X5R, 0201; Manufacturer: MuRata; Polarized: N; CompType: Capacitor; Value: 4uF; U/M: EA; Cap_F: 0.000004; Tolerance_%: 20; VDC_V: 6.3; Value2: 6.3V; TaMin_C: -55; TaMax_C: 85; Cap_Case: 0201; SizeArea_mm2: 0.18; SizeAreaWB_mm2: 2.08; SizeX_mm: 0.6; SizeY_mm: 0.3; SizeZ_mm: 0.55; AEC Category: Q200
signal-integrity model Cap
simulation model Cap
footprint 0201_055
pins: 1, 2

## GRM035R60J475ME15D
designator C?  ValueDisplayed: 4.7µF  (hidden comment: GRM035R60J475ME15D)
CAP, CERM, 4.7 µF, 6.3 V,+/- 20%, X5R, 0201; Manufacturer: MuRata; Polarized: N; CompType: Capacitor; Value: 4.7uF; U/M: EA; Cap_F: 0.0000047; Tolerance_%: 20; VDC_V: 6.3; Value2: 6.3V; TaMin_C: -55; TaMax_C: 85; Cap_Case: 0201; SizeArea_mm2: 0.18; SizeAreaWB_mm2: 2.08; SizeX_mm: 0.6; SizeY_mm: 0.3; SizeZ_mm: 0.26; AEC Category: Q200
signal-integrity model Cap
simulation model Cap
footprint 0201
footprint 0201M
footprint 0201L
footprint 0201_Silk
pins: 1, 2

## GRM42A7U3F101JW31L
designator C?  ValueDisplayed: 100pF  (hidden comment: GRM42A7U3F101JW31L)
CAP, CERM, 100 pF, 3150 V,+/- 5%, U2J, 1808; Manufacturer: MuRata; Polarized: N; CompType: Capacitor; Value: 100pF; U/M: EA; Cap_F: 0.0000000001; Tolerance_%: 5; VDC_V: 3150; Value2: 3150V; TaMin_C: -55; TaMax_C: 125; Cap_Case: 1808; SizeArea_mm2: 9; SizeAreaWB_mm2: 16.5; SizeX_mm: 4.5; SizeY_mm: 2; SizeZ_mm: 2.03; AEC Category: Q200
signal-integrity model Cap
simulation model Cap
footprint 1808
footprint 1808_M
footprint 1808_L
pins: 1, 2

## GRM42A7U3F560JW31L
designator C?  ValueDisplayed: 56pF  (hidden comment: GRM42A7U3F560JW31L)
CAP, CERM, 56 pF, 3150 V,+/- 5%, U2J, 1808; Manufacturer: MuRata; Polarized: N; CompType: Capacitor; Value: 56pF; U/M: EA; Cap_F: 0.000000000056; Tolerance_%: 5; VDC_V: 3150; Value2: 3150V; TaMin_C: -55; TaMax_C: 125; Cap_Case: 1808; SizeArea_mm2: 9; SizeAreaWB_mm2: 16.5; SizeX_mm: 4.5; SizeY_mm: 2; SizeZ_mm: 2.03; AEC Category: Q200
signal-integrity model Cap
simulation model Cap
footprint 1808
footprint 1808_M
footprint 1808_L
pins: 1, 2

## GRM42A7U3F680JW31L
designator C?  ValueDisplayed: 68pF  (hidden comment: GRM42A7U3F680JW31L)
CAP, CERM, 68 pF, 3150 V,+/- 5%, U2J, 1808; Manufacturer: MuRata; Polarized: N; CompType: Capacitor; Value: 68pF; U/M: EA; Cap_F: 0.000000000068; Tolerance_%: 5; VDC_V: 3150; Value2: 3150V; TaMin_C: -55; TaMax_C: 125; Cap_Case: 1808; SizeArea_mm2: 9; SizeAreaWB_mm2: 16.5; SizeX_mm: 4.5; SizeY_mm: 2; SizeZ_mm: 2.03; AEC Category: Q200
signal-integrity model Cap
simulation model Cap
footprint 1808
footprint 1808_M
footprint 1808_L
pins: 1, 2

## GRM42A7U3F820JW31L
designator C?  ValueDisplayed: 82pF  (hidden comment: GRM42A7U3F820JW31L)
CAP, CERM, 82 pF, 3150 V,+/- 5%, U2J, 1808; Manufacturer: MuRata; Polarized: N; CompType: Capacitor; Value: 82pF; U/M: EA; Cap_F: 0.000000000082; Tolerance_%: 5; VDC_V: 3150; Value2: 3150V; TaMin_C: -55; TaMax_C: 125; Cap_Case: 1808; SizeArea_mm2: 9; SizeAreaWB_mm2: 16.5; SizeX_mm: 4.5; SizeY_mm: 2; SizeZ_mm: 2.03; AEC Category: Q200
signal-integrity model Cap
simulation model Cap
footprint 1808
footprint 1808_M
footprint 1808_L
pins: 1, 2

## GRM43DR72A474KA01L
designator C?  ValueDisplayed: 0.47µF  (hidden comment: GRM43DR72A474KA01L)
CAP, CERM, 0.47 µF, 100 V,+/- 10%, X7R, 1812; Manufacturer: MuRata; Polarized: N; CompType: Capacitor; Value: 0.47uF; U/M: EA; Cap_F: 0.00000047; Tolerance_%: 10; VDC_V: 100; Value2: 100V; TaMin_C: -55; TaMax_C: 125; Cap_Case: 1812; SizeArea_mm2: 14.4; SizeAreaWB_mm2: 23.1; SizeX_mm: 4.5; SizeY_mm: 3.2; SizeZ_mm: 1.35; AEC Category: Q200
signal-integrity model Cap
simulation model Cap
footprint 1812
footprint 1812M
footprint 1812L
footprint 1812_HV
pins: 1, 2

## GRM43DR72E224KW01L
designator C?  ValueDisplayed: 0.22µF  (hidden comment: GRM43DR72E224KW01L)
CAP, CERM, 0.22 µF, 250 V,+/- 10%, X7R, 1812; Manufacturer: MuRata; Polarized: N; CompType: Capacitor; Value: 0.22uF; U/M: EA; Cap_F: 0.00000022; Tolerance_%: 10; VDC_V: 250; Value2: 250V; TaMin_C: -55; TaMax_C: 125; Cap_Case: 1812; SizeArea_mm2: 14.4; SizeAreaWB_mm2: 23.1; SizeX_mm: 4.5; SizeY_mm: 3.2; SizeZ_mm: 1.35; AEC Category: Q200
signal-integrity model Cap
simulation model Cap
footprint 1812
footprint 1812M
footprint 1812L
footprint 1812_HV
pins: 1, 2

## GRM43DR72E334KW01L
designator C?  ValueDisplayed: 0.33µF  (hidden comment: GRM43DR72E334KW01L)
CAP, CERM, 0.33 µF, 250 V,+/- 10%, X7R, 1812; Manufacturer: MuRata; Polarized: N; CompType: Capacitor; Value: 0.33uF; U/M: EA; Cap_F: 0.00000033; Tolerance_%: 10; VDC_V: 250; Value2: 250V; TaMin_C: -55; TaMax_C: 125; Cap_Case: 1812; SizeArea_mm2: 14.4; SizeAreaWB_mm2: 23.1; SizeX_mm: 4.5; SizeY_mm: 3.2; SizeZ_mm: 1.35; AEC Category: Q200; Green_Lifecycle: Not Set; Green_REACh: Incomplete
signal-integrity model Cap
simulation model Cap
footprint 1812
footprint 1812M
footprint 1812L
footprint 1812_HV
pins: 1, 2

## GRM43DR72E474KW01L
designator C?  ValueDisplayed: 0.47µF  (hidden comment: GRM43DR72E474KW01L)
CAP, CERM, 0.47 µF, 250 V,+/- 10%, X7R, 1812; Manufacturer: MuRata; Polarized: N; CompType: Capacitor; Value: 0.47uF; U/M: EA; Cap_F: 0.00000047; Tolerance_%: 10; VDC_V: 250; Value2: 250V; TaMin_C: -55; TaMax_C: 125; Cap_Case: 1812; SizeArea_mm2: 14.4; SizeAreaWB_mm2: 23.1; SizeX_mm: 4.5; SizeY_mm: 3.2; SizeZ_mm: 1.35; AEC Category: Q200
signal-integrity model Cap
simulation model Cap
footprint 1812
footprint 1812M
footprint 1812L
footprint 1812_HV
pins: 1, 2

## GRM43DR72J104KW01L
designator C?  ValueDisplayed: 0.1µF  (hidden comment: GRM43DR72J104KW01L)
CAP, CERM, 0.1 µF, 630 V,+/- 10%, X7R, 1812; Manufacturer: MuRata; Polarized: N; CompType: Capacitor; Value: 0.1uF; U/M: EA; Cap_F: 0.0000001; Tolerance_%: 10; VDC_V: 630; Value2: 630V; TaMin_C: -55; TaMax_C: 125; Cap_Case: 1812; SizeArea_mm2: 14.4; SizeAreaWB_mm2: 23.1; SizeX_mm: 4.5; SizeY_mm: 3.2; SizeZ_mm: 1.35; AEC Category: Q200; Green_Lifecycle: Not Set; Green_REACh: Incomplete
signal-integrity model Cap
simulation model Cap
footprint 1812
footprint 1812M
footprint 1812L
footprint 1812_HV
pins: 1, 2

## GRM43DR73A333KW01L
designator C?  ValueDisplayed: 0.033µF  (hidden comment: GRM43DR73A333KW01L)
CAP, CERM, 0.033 µF, 1000 V,+/- 10%, X7R, 1812; Manufacturer: MuRata; Polarized: N; CompType: Capacitor; Value: 0.033uF; U/M: EA; Cap_F: 0.000000033; Tolerance_%: 10; VDC_V: 1000; Value2: 1000V; TaMin_C: -55; TaMax_C: 125; Cap_Case: 1812; SizeArea_mm2: 14.4; SizeAreaWB_mm2: 23.1; SizeX_mm: 4.5; SizeY_mm: 3.2; SizeZ_mm: 1.35; AEC Category: Q200
signal-integrity model Cap
simulation model Cap
footprint 1812
footprint 1812M
footprint 1812L
footprint 1812_HV
pins: 1, 2

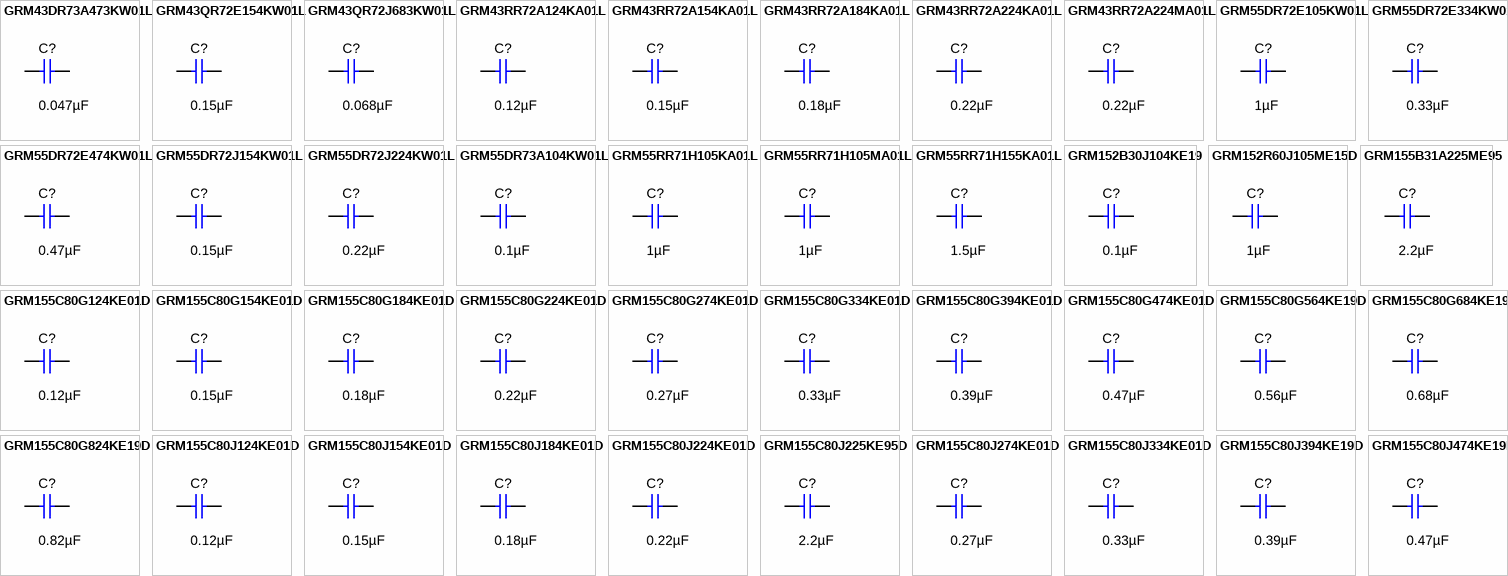
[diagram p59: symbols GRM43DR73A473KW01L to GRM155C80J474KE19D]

## GRM43DR73A473KW01L
designator C?  ValueDisplayed: 0.047µF  (hidden comment: GRM43DR73A473KW01L)
CAP, CERM, 0.047 µF, 1000 V,+/- 10%, X7R, 1812; Manufacturer: MuRata; Polarized: N; CompType: Capacitor; Value: 0.047uF; U/M: EA; Cap_F: 0.000000047; Tolerance_%: 10; VDC_V: 1000; Value2: 1000V; TaMin_C: -55; TaMax_C: 125; Cap_Case: 1812; SizeArea_mm2: 14.4; SizeAreaWB_mm2: 23.1; SizeX_mm: 4.5; SizeY_mm: 3.2; SizeZ_mm: 1.35; AEC Category: Q200
signal-integrity model Cap
simulation model Cap
footprint 1812
footprint 1812M
footprint 1812L
footprint 1812_HV
pins: 1, 2

## GRM43QR72E154KW01L
designator C?  ValueDisplayed: 0.15µF  (hidden comment: GRM43QR72E154KW01L)
CAP, CERM, 0.15 µF, 250 V,+/- 10%, X7R, 1812; Manufacturer: MuRata; Polarized: N; CompType: Capacitor; Value: 0.15uF; U/M: EA; Cap_F: 0.00000015; Tolerance_%: 10; VDC_V: 250; Value2: 250V; TaMin_C: -55; TaMax_C: 125; Cap_Case: 1812; SizeArea_mm2: 14.4; SizeAreaWB_mm2: 23.1; SizeX_mm: 4.5; SizeY_mm: 3.2; SizeZ_mm: 1.35; AEC Category: Q200
signal-integrity model Cap
simulation model Cap
footprint 1812
footprint 1812M
footprint 1812L
footprint 1812_HV
pins: 1, 2

## GRM43QR72J683KW01L
designator C?  ValueDisplayed: 0.068µF  (hidden comment: GRM43QR72J683KW01L)
CAP, CERM, 0.068 µF, 630 V,+/- 10%, X7R, 1812; Manufacturer: MuRata; Polarized: N; CompType: Capacitor; Value: 0.068uF; U/M: EA; Cap_F: 0.000000068; Tolerance_%: 10; VDC_V: 630; Value2: 630V; TaMin_C: -55; TaMax_C: 125; Cap_Case: 1812; SizeArea_mm2: 14.4; SizeAreaWB_mm2: 23.1; SizeX_mm: 4.5; SizeY_mm: 3.2; SizeZ_mm: 1.35; AEC Category: Q200
signal-integrity model Cap
simulation model Cap
footprint 1812
footprint 1812M
footprint 1812L
footprint 1812_HV
pins: 1, 2

## GRM43RR72A124KA01L
designator C?  ValueDisplayed: 0.12µF  (hidden comment: GRM43RR72A124KA01L)
CAP, CERM, 0.12 µF, 100 V,+/- 10%, X7R, 1812; Manufacturer: MuRata; Polarized: N; CompType: Capacitor; Value: 0.12uF; U/M: EA; Cap_F: 0.00000012; Tolerance_%: 10; VDC_V: 100; Value2: 100V; TaMin_C: -55; TaMax_C: 125; Cap_Case: 1812; SizeArea_mm2: 14.4; SizeAreaWB_mm2: 23.1; SizeX_mm: 4.5; SizeY_mm: 3.2; SizeZ_mm: 1.35; AEC Category: Q200
signal-integrity model Cap
simulation model Cap
footprint 1812
footprint 1812M
footprint 1812L
footprint 1812_HV
pins: 1, 2

## GRM43RR72A154KA01L
designator C?  ValueDisplayed: 0.15µF  (hidden comment: GRM43RR72A154KA01L)
CAP, CERM, 0.15 µF, 100 V,+/- 10%, X7R, 1812; Manufacturer: MuRata; Polarized: N; CompType: Capacitor; Value: 0.15uF; U/M: EA; Cap_F: 0.00000015; Tolerance_%: 10; VDC_V: 100; Value2: 100V; TaMin_C: -55; TaMax_C: 125; Cap_Case: 1812; SizeArea_mm2: 14.4; SizeAreaWB_mm2: 23.1; SizeX_mm: 4.5; SizeY_mm: 3.2; SizeZ_mm: 1.35; AEC Category: Q200
signal-integrity model Cap
simulation model Cap
footprint 1812
footprint 1812M
footprint 1812L
footprint 1812_HV
pins: 1, 2

## GRM43RR72A184KA01L
designator C?  ValueDisplayed: 0.18µF  (hidden comment: GRM43RR72A184KA01L)
CAP, CERM, 0.18 µF, 100 V,+/- 10%, X7R, 1812; Manufacturer: MuRata; Polarized: N; CompType: Capacitor; Value: 0.18uF; U/M: EA; Cap_F: 0.00000018; Tolerance_%: 10; VDC_V: 100; Value2: 100V; TaMin_C: -55; TaMax_C: 125; Cap_Case: 1812; SizeArea_mm2: 14.4; SizeAreaWB_mm2: 23.1; SizeX_mm: 4.5; SizeY_mm: 3.2; SizeZ_mm: 1.35; AEC Category: Q200
signal-integrity model Cap
simulation model Cap
footprint 1812
footprint 1812M
footprint 1812L
footprint 1812_HV
pins: 1, 2

## GRM43RR72A224KA01L
designator C?  ValueDisplayed: 0.22µF  (hidden comment: GRM43RR72A224KA01L)
CAP, CERM, 0.22 µF, 100 V,+/- 10%, X7R, 1812; Manufacturer: MuRata; Polarized: N; CompType: Capacitor; Value: 0.22uF; U/M: EA; Cap_F: 0.00000022; Tolerance_%: 10; VDC_V: 100; Value2: 100V; TaMin_C: -55; TaMax_C: 125; Cap_Case: 1812; SizeArea_mm2: 14.4; SizeAreaWB_mm2: 23.1; SizeX_mm: 4.5; SizeY_mm: 3.2; SizeZ_mm: 1.35; AEC Category: Q200
signal-integrity model Cap
simulation model Cap
footprint 1812
footprint 1812M
footprint 1812L
footprint 1812_HV
pins: 1, 2

## GRM43RR72A224MA01L
designator C?  ValueDisplayed: 0.22µF  (hidden comment: GRM43RR72A224MA01L)
CAP, CERM, 0.22 µF, 100 V,+/- 20%, X7R, 1812; Manufacturer: MuRata; Polarized: N; CompType: Capacitor; Value: 0.22uF; U/M: EA; Cap_F: 0.00000022; Tolerance_%: 20; VDC_V: 100; Value2: 100V; TaMin_C: -55; TaMax_C: 125; Cap_Case: 1812; SizeArea_mm2: 14.4; SizeAreaWB_mm2: 23.1; SizeX_mm: 4.5; SizeY_mm: 3.2; SizeZ_mm: 1.35; AEC Category: Q200
signal-integrity model Cap
simulation model Cap
footprint 1812
footprint 1812M
footprint 1812L
footprint 1812_HV
pins: 1, 2

## GRM55DR72E105KW01L
designator C?  ValueDisplayed: 1µF  (hidden comment: GRM55DR72E105KW01L)
CAP, CERM, 1 µF, 250 V,+/- 10%, X7R, 2220; Manufacturer: MuRata; Polarized: N; CompType: Capacitor; Value: 1uF; U/M: EA; Cap_F: 0.000001; Tolerance_%: 10; ESR_ohm: 0.007086; Value1: 0.007086 ohm; VDC_V: 250; Value2: 250V; IRMS_A: 2.0605; TaMin_C: -55; TaMax_C: 125; Cap_Case: 2220; SizeArea_mm2: 28.5; SizeAreaWB_mm2: 53.9; SizeX_mm: 5.7; SizeY_mm: 5; SizeZ_mm: 2; AEC Category: Q200; Green_Lifecycle: Not Set; Green_REACh: Incomplete
signal-integrity model Cap
simulation model Cap
footprint 2220_200
footprint 2220_200M
footprint 2220_200L
pins: 1, 2

## GRM55DR72E334KW01L
designator C?  ValueDisplayed: 0.33µF  (hidden comment: GRM55DR72E334KW01L)
CAP, CERM, 0.33 µF, 250 V,+/- 10%, X7R, 2220; Manufacturer: MuRata; Polarized: N; CompType: Capacitor; Value: 0.33uF; U/M: EA; Cap_F: 0.00000033; Tolerance_%: 10; VDC_V: 250; Value2: 250V; TaMin_C: -55; TaMax_C: 125; Cap_Case: 2220; SizeArea_mm2: 28.5; SizeAreaWB_mm2: 53.9; SizeX_mm: 5.7; SizeY_mm: 5; SizeZ_mm: 1.35; AEC Category: Q200
signal-integrity model Cap
simulation model Cap
footprint 2220
footprint 2220_M
footprint 2220_L
pins: 1, 2

## GRM55DR72E474KW01L
designator C?  ValueDisplayed: 0.47µF  (hidden comment: GRM55DR72E474KW01L)
CAP, CERM, 0.47 µF, 250 V,+/- 10%, X7R, 2220; Manufacturer: MuRata; Polarized: N; CompType: Capacitor; Value: 0.47uF; U/M: EA; Cap_F: 0.00000047; Tolerance_%: 10; VDC_V: 250; Value2: 250V; TaMin_C: -55; TaMax_C: 125; Cap_Case: 2220; SizeArea_mm2: 28.5; SizeAreaWB_mm2: 53.9; SizeX_mm: 5.7; SizeY_mm: 5; SizeZ_mm: 1.35; AEC Category: Q200
signal-integrity model Cap
simulation model Cap
footprint 2220
footprint 2220_M
footprint 2220_L
pins: 1, 2

## GRM55DR72J154KW01L
designator C?  ValueDisplayed: 0.15µF  (hidden comment: GRM55DR72J154KW01L)
CAP, CERM, 0.15 µF, 630 V,+/- 10%, X7R, 2220; Manufacturer: MuRata; Polarized: N; CompType: Capacitor; Value: 0.15uF; U/M: EA; Cap_F: 0.00000015; Tolerance_%: 10; VDC_V: 630; Value2: 630V; TaMin_C: -55; TaMax_C: 125; Cap_Case: 2220; SizeArea_mm2: 28.5; SizeAreaWB_mm2: 53.9; SizeX_mm: 5.7; SizeY_mm: 5; SizeZ_mm: 1.35; AEC Category: Q200
signal-integrity model Cap
simulation model Cap
footprint 2220
footprint 2220_M
footprint 2220_L
pins: 1, 2

## GRM55DR72J224KW01L
designator C?  ValueDisplayed: 0.22µF  (hidden comment: GRM55DR72J224KW01L)
CAP, CERM, 0.22 µF, 630 V,+/- 10%, X7R, 2220; Manufacturer: MuRata; Polarized: N; CompType: Capacitor; Value: 0.22uF; U/M: EA; Cap_F: 0.00000022; Tolerance_%: 10; VDC_V: 630; Value2: 630V; TaMin_C: -55; TaMax_C: 125; Cap_Case: 2220; SizeArea_mm2: 28.5; SizeAreaWB_mm2: 53.9; SizeX_mm: 5.7; SizeY_mm: 5; SizeZ_mm: 1.35; AEC Category: Q200
signal-integrity model Cap
simulation model Cap
footprint 2220
footprint 2220_M
footprint 2220_L
pins: 1, 2

## GRM55DR73A104KW01L
designator C?  ValueDisplayed: 0.1µF  (hidden comment: GRM55DR73A104KW01L)
CAP, CERM, 0.1 µF, 1000 V,+/- 10%, X7R, 2220; Manufacturer: MuRata; Polarized: N; CompType: Capacitor; Value: 0.1uF; U/M: EA; Cap_F: 0.0000001; Tolerance_%: 10; VDC_V: 1000; Value2: 1000V; TaMin_C: -55; TaMax_C: 125; Cap_Case: 2220; SizeArea_mm2: 28.5; SizeAreaWB_mm2: 53.9; SizeX_mm: 5.7; SizeY_mm: 5; SizeZ_mm: 1.35; AEC Category: Q200
signal-integrity model Cap
simulation model Cap
footprint 2220
footprint 2220_M
footprint 2220_L
pins: 1, 2

## GRM55RR71H105KA01L
designator C?  ValueDisplayed: 1µF  (hidden comment: GRM55RR71H105KA01L)
CAP, CERM, 1 µF, 50 V,+/- 10%, X7R, 2220; Manufacturer: MuRata; Polarized: N; CompType: Capacitor; Value: 1uF; U/M: EA; Cap_F: 0.000001; Tolerance_%: 10; ESR_ohm: 0.003; Value1: 0.003 ohm; VDC_V: 50; Value2: 50V; TaMin_C: -55; TaMax_C: 125; Cap_Case: 2220; SizeArea_mm2: 28.5; SizeAreaWB_mm2: 53.9; SizeX_mm: 5.7; SizeY_mm: 5; SizeZ_mm: 1.35; AEC Category: Q200
signal-integrity model Cap
simulation model Cap
footprint 2220
footprint 2220_M
footprint 2220_L
pins: 1, 2

## GRM55RR71H105MA01L
designator C?  ValueDisplayed: 1µF  (hidden comment: GRM55RR71H105MA01L)
CAP, CERM, 1 µF, 50 V,+/- 20%, X7R, 2220; Manufacturer: MuRata; Polarized: N; CompType: Capacitor; Value: 1uF; U/M: EA; Cap_F: 0.000001; Tolerance_%: 20; ESR_ohm: 0.003; Value1: 0.003 ohm; VDC_V: 50; Value2: 50V; TaMin_C: -55; TaMax_C: 125; Cap_Case: 2220; SizeArea_mm2: 28.5; SizeAreaWB_mm2: 53.9; SizeX_mm: 5.7; SizeY_mm: 5; SizeZ_mm: 1.35; AEC Category: Q200
signal-integrity model Cap
simulation model Cap
footprint 2220
footprint 2220_M
footprint 2220_L
pins: 1, 2

## GRM55RR71H155KA01L
designator C?  ValueDisplayed: 1.5µF  (hidden comment: GRM55RR71H155KA01L)
CAP, CERM, 1.5 µF, 50 V,+/- 10%, X7R, 2220; Manufacturer: MuRata; Polarized: N; CompType: Capacitor; Value: 1.5uF; U/M: EA; Cap_F: 0.0000015; Tolerance_%: 10; ESR_ohm: 0.002; Value1: 0.002 ohm; VDC_V: 50; Value2: 50V; TaMin_C: -55; TaMax_C: 125; Cap_Case: 2220; SizeArea_mm2: 28.5; SizeAreaWB_mm2: 53.9; SizeX_mm: 5.7; SizeY_mm: 5; SizeZ_mm: 1.35; AEC Category: Q200
signal-integrity model Cap
simulation model Cap
footprint 2220
footprint 2220_M
footprint 2220_L
pins: 1, 2

## GRM152B30J104KE19
designator C?  ValueDisplayed: 0.1µF  (hidden comment: GRM152B30J104KE19)
CAP, CERM, 0.1 µF, 6.3 V,+/- 10%, B, 0402; Manufacturer: MuRata; Polarized: N; CompType: Capacitor; Value: 0.1uF; U/M: EA; Cap_F: 0.0000001; Tolerance_%: 10; VDC_V: 6.3; Value2: 6.3V; TaMin_C: -25; TaMax_C: 85; Cap_Case: 0402; SizeArea_mm2: 0.5; SizeAreaWB_mm2: 3; SizeX_mm: 1; SizeZ_mm: 0.6; AEC Category: Q200
signal-integrity model Cap
simulation model Cap
footprint 0402
footprint 0402M
footprint 0402L
footprint 0402S
pins: 1, 2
